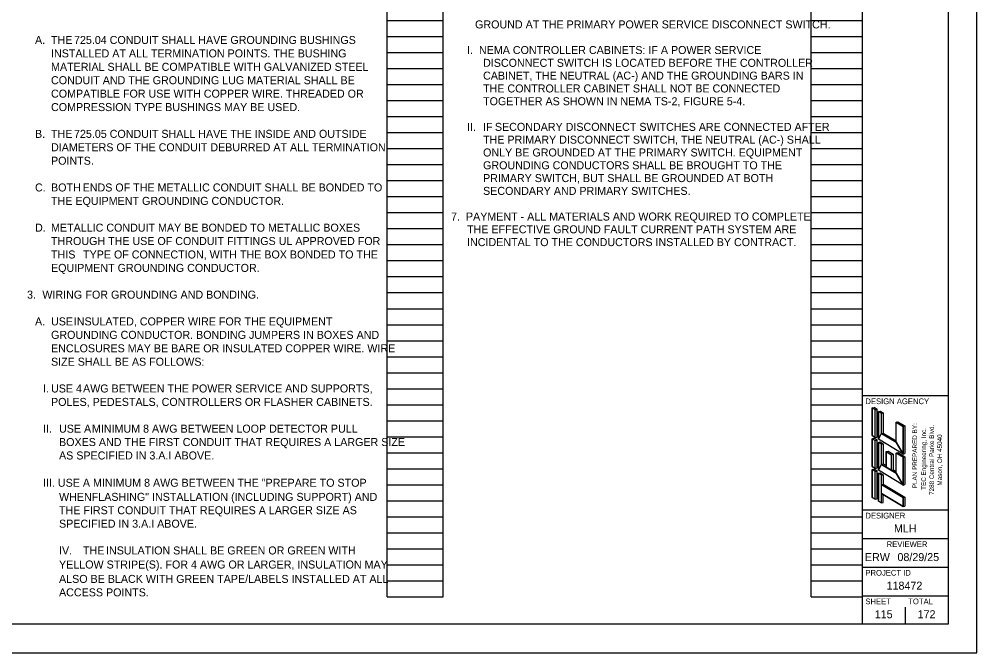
# Model space of a CAD drawing. Extents: x 0 to 34, y 0 to 22.
# Drawn here: x 17.24 to 34, y 0 to 11.08 of the extents above; entities that cross this region are included whole.
import ezdxf

# ---------------------------------------------------------------- set-up
doc = ezdxf.new("R2010")
doc.units = 0
for name, color, linetype in [('Default', 7, 'Continuous'), ('SH_Border', 7, 'Continuous'), ('SH_Cut_Line', 7, 'Continuous'), ('SH_Data', 7, 'Continuous'), ('SH_Text', 7, 'Continuous')]:
    doc.layers.add(name, color=color, linetype=linetype)

msp = doc.modelspace()

# ---------------------------------------------------------------- linework, layer by layer
at = {"layer": 'SH_Border'}
for p, q in [((32, 0.5), (32, 21.5)), ((32, 4.5), (33.5, 4.5)), ((32, 2.5), (33.5, 2.5)), ((32, 2), (33.5, 2)), ((32, 1.5), (33.5, 1.5)), ((32, 1), (33.5, 1))]:
    msp.add_line(p, q, dxfattribs=at)
msp.add_lwpolyline([(1.5, 21.5), (33.5, 21.5), (33.5, 0.5), (1.5, 0.5)], close=True, dxfattribs=at)
at = {"layer": 'SH_Cut_Line'}
msp.add_lwpolyline([(0, 0), (34, 0), (34, 22), (0, 22)], close=True, dxfattribs=at)
at = {"layer": 'SH_Data'}
for p, q in [((23.68, 0.98), (23.68, 21.14)), ((24.66, 0.98), (24.66, 21.14)), ((31.1, 0.98), (31.1, 21.14)), ((32, 0.98), (32, 21.14)), ((23.68, 11.06), (24.66, 11.06)), ((31.1, 11.06), (32, 11.06)), ((23.68, 10.78), (24.66, 10.78)), ((31.1, 10.78), (32, 10.78)), ((23.68, 10.5), (24.66, 10.5)), ((31.1, 10.5), (32, 10.5)), ((23.68, 10.22), (24.66, 10.22)), ((31.1, 10.22), (32, 10.22)), ((23.68, 9.94), (24.66, 9.94)), ((31.1, 9.94), (32, 9.94)), ((23.68, 9.66), (24.66, 9.66)), ((31.1, 9.66), (32, 9.66)), ((23.68, 9.38), (24.66, 9.38)), ((31.1, 9.38), (32, 9.38)), ((23.68, 9.1), (24.66, 9.1)), ((31.1, 9.1), (32, 9.1)), ((23.68, 8.82), (24.66, 8.82)), ((31.1, 8.82), (32, 8.82)), ((23.68, 8.54), (24.66, 8.54)), ((31.1, 8.54), (32, 8.54)), ((23.68, 8.26), (24.66, 8.26)), ((31.1, 8.26), (32, 8.26)), ((23.68, 7.98), (24.66, 7.98)), ((31.1, 7.98), (32, 7.98)), ((23.68, 7.7), (24.66, 7.7)), ((31.1, 7.7), (32, 7.7)), ((23.68, 7.42), (24.66, 7.42)), ((31.1, 7.42), (32, 7.42)), ((23.68, 7.14), (24.66, 7.14)), ((31.1, 7.14), (32, 7.14)), ((23.68, 6.86), (24.66, 6.86)), ((31.1, 6.86), (32, 6.86)), ((23.68, 6.58), (24.66, 6.58)), ((31.1, 6.58), (32, 6.58)), ((23.68, 6.3), (24.66, 6.3)), ((31.1, 6.3), (32, 6.3)), ((23.68, 6.02), (24.66, 6.02)), ((31.1, 6.02), (32, 6.02)), ((23.68, 5.74), (24.66, 5.74)), ((31.1, 5.74), (32, 5.74)), ((23.68, 5.46), (24.66, 5.46)), ((31.1, 5.46), (32, 5.46)), ((23.68, 5.18), (24.66, 5.18)), ((31.1, 5.18), (32, 5.18)), ((23.68, 4.9), (24.66, 4.9)), ((31.1, 4.9), (32, 4.9)), ((23.68, 4.62), (24.66, 4.62)), ((31.1, 4.62), (32, 4.62)), ((23.68, 4.34), (24.66, 4.34)), ((31.1, 4.34), (32, 4.34)), ((23.68, 4.06), (24.66, 4.06)), ((31.1, 4.06), (32, 4.06)), ((23.68, 3.78), (24.66, 3.78)), ((31.1, 3.78), (32, 3.78)), ((23.68, 3.5), (24.66, 3.5)), ((31.1, 3.5), (32, 3.5)), ((32.75, 3.5), (32.75, 3.5)), ((23.68, 3.22), (24.66, 3.22)), ((31.1, 3.22), (32, 3.22)), ((23.68, 2.94), (24.66, 2.94)), ((31.1, 2.94), (32, 2.94)), ((23.68, 2.66), (24.66, 2.66)), ((31.1, 2.66), (32, 2.66)), ((23.68, 2.38), (24.66, 2.38)), ((31.1, 2.38), (32, 2.38)), ((23.68, 2.1), (24.66, 2.1)), ((31.1, 2.1), (32, 2.1)), ((23.68, 1.82), (24.66, 1.82)), ((31.1, 1.82), (32, 1.82)), ((23.68, 1.54), (24.66, 1.54)), ((31.1, 1.54), (32, 1.54)), ((23.68, 1.26), (24.66, 1.26)), ((31.1, 1.26), (32, 1.26)), ((23.68, 0.98), (24.66, 0.98)), ((31.1, 0.98), (32, 0.98)), ((32.375, 0.675), (32.375, 0.675)), ((32.75, 0.5), (32.75, 0.8))]:
    msp.add_line(p, q, dxfattribs=at)
at = {"layer": 'SH_Text'}
for p, q in [((32.169, 4.285), (32.201, 4.294)), ((32.169, 3.799), (32.169, 4.285)), ((32.223, 4.253), (32.169, 4.285)), ((32.255, 4.261), (32.201, 4.294)), ((32.223, 4.253), (32.255, 4.261)), ((32.223, 3.767), (32.223, 4.253)), ((32.255, 3.775), (32.255, 4.261)), ((32.277, 4.221), (32.309, 4.229)), ((32.331, 4.188), (32.277, 4.221)), ((32.277, 3.735), (32.277, 4.221)), ((32.309, 4.229), (32.363, 4.196)), ((32.331, 4.188), (32.363, 4.196)), ((32.363, 4.196), (32.363, 3.845)), ((32.331, 3.837), (32.331, 4.188)), ((32.587, 4.034), (32.62, 4.042)), ((32.587, 3.683), (32.587, 4.034)), ((32.709, 3.961), (32.587, 4.034)), ((32.62, 4.042), (32.741, 3.97)), ((32.709, 3.961), (32.741, 3.97)), ((32.709, 3.475), (32.709, 3.961)), ((32.741, 3.97), (32.741, 3.484)), ((32.223, 3.767), (32.169, 3.799)), ((32.169, 3.745), (32.201, 3.754)), ((32.169, 3.259), (32.169, 3.745)), ((32.223, 3.713), (32.169, 3.745)), ((32.255, 3.722), (32.201, 3.754)), ((32.223, 3.767), (32.255, 3.775)), ((32.223, 3.713), (32.255, 3.722)), ((32.223, 3.227), (32.223, 3.713)), ((32.255, 3.236), (32.255, 3.722)), ((32.709, 3.475), (32.277, 3.735)), ((32.277, 3.681), (32.309, 3.689)), ((32.309, 3.689), (32.363, 3.656)), ((32.331, 3.837), (32.363, 3.845)), ((32.587, 3.683), (32.331, 3.837)), ((32.363, 3.845), (32.587, 3.711)), ((32.277, 3.195), (32.277, 3.681)), ((32.331, 3.648), (32.277, 3.681)), ((32.331, 3.648), (32.363, 3.656)), ((32.331, 3.297), (32.331, 3.648)), ((32.363, 3.656), (32.363, 3.305)), ((32.415, 3.519), (32.448, 3.527)), ((32.448, 3.527), (32.535, 3.474)), ((32.415, 3.519), (32.415, 3.247)), ((32.415, 3.519), (32.503, 3.466)), ((32.503, 3.466), (32.535, 3.474)), ((32.503, 3.466), (32.503, 3.194)), ((32.535, 3.474), (32.535, 3.202)), ((32.587, 3.494), (32.62, 3.502)), ((32.587, 3.143), (32.587, 3.494)), ((32.709, 3.421), (32.587, 3.494)), ((32.62, 3.502), (32.741, 3.43)), ((32.709, 3.475), (32.741, 3.484)), ((32.709, 3.421), (32.741, 3.43)), ((32.709, 2.935), (32.709, 3.421)), ((32.741, 3.43), (32.741, 2.944)), ((32.223, 3.227), (32.169, 3.259)), ((32.169, 3.205), (32.201, 3.215)), ((32.169, 2.719), (32.169, 3.205)), ((32.223, 3.173), (32.169, 3.205)), ((32.255, 3.181), (32.201, 3.215)), ((32.223, 3.227), (32.255, 3.236)), ((32.709, 2.935), (32.277, 3.195)), ((32.331, 3.297), (32.363, 3.305)), ((32.415, 3.247), (32.331, 3.297)), ((32.363, 3.305), (32.415, 3.274)), ((32.503, 3.194), (32.535, 3.202)), ((32.587, 3.143), (32.503, 3.194)), ((32.535, 3.202), (32.587, 3.171)), ((32.222, 3.173), (32.255, 3.181)), ((32.223, 2.687), (32.223, 3.173)), ((32.255, 2.695), (32.255, 3.181)), ((32.277, 3.141), (32.309, 3.151)), ((32.331, 3.108), (32.277, 3.141)), ((32.277, 2.655), (32.277, 3.141)), ((32.309, 3.151), (32.363, 3.116)), ((32.331, 3.108), (32.363, 3.116)), ((32.331, 2.944), (32.331, 3.108)), ((32.363, 3.116), (32.363, 2.952)), ((32.331, 2.944), (32.363, 2.952)), ((32.331, 2.944), (32.709, 2.717)), ((32.363, 2.952), (32.741, 2.725)), ((32.709, 2.935), (32.741, 2.944)), ((32.223, 2.687), (32.169, 2.719)), ((32.223, 2.687), (32.255, 2.695)), ((32.331, 2.787), (32.709, 2.56)), ((32.331, 2.622), (32.331, 2.787)), ((32.363, 2.63), (32.363, 2.767)), ((32.709, 2.717), (32.741, 2.725)), ((32.709, 2.56), (32.709, 2.717)), ((32.741, 2.725), (32.741, 2.568)), ((32.331, 2.622), (32.277, 2.655)), ((32.331, 2.622), (32.363, 2.63)), ((32.709, 2.56), (32.741, 2.568))]:
    msp.add_line(p, q, dxfattribs=at)
for points in [[(32.169, 3.799), (32.223, 3.767), (32.223, 4.253), (32.169, 4.285)], [(32.277, 3.735), (32.331, 3.837), (32.331, 4.188), (32.277, 4.221)], [(32.709, 3.475), (32.587, 3.683), (32.587, 4.034), (32.709, 3.961)], [(32.169, 3.259), (32.223, 3.227), (32.223, 3.713), (32.169, 3.745)], [(32.277, 3.735), (32.331, 3.837), (32.587, 3.683), (32.709, 3.475)], [(32.277, 3.195), (32.331, 3.297), (32.331, 3.648), (32.277, 3.681)], [(32.415, 3.247), (32.415, 3.519), (32.503, 3.466), (32.503, 3.194)], [(32.709, 2.935), (32.587, 3.143), (32.587, 3.494), (32.709, 3.421)], [(32.169, 2.719), (32.223, 2.687), (32.223, 3.173), (32.169, 3.205)], [(32.277, 3.195), (32.331, 3.297), (32.587, 3.143), (32.709, 2.935)], [(32.277, 2.655), (32.331, 2.622), (32.331, 3.108), (32.277, 3.141)], [(32.331, 2.787), (32.331, 2.944), (32.709, 2.717), (32.709, 2.56)]]:
    msp.add_lwpolyline(points, close=True, dxfattribs=at)

# ---------------------------------------------------------------- texts
at = {"layer": 'Default'}
for s, p in [('PLAN PREPARED BY:', (32.954, 2.88)), ('TEC Engineering, Inc.', (33.11, 2.851)), ('7288 Central Parke Blvd.', (33.25, 2.762)), ('Mason, OH 45040', (33.39, 2.925))]:
    msp.add_text(s, height=0.08, rotation=90, dxfattribs=at).set_placement(p)
at = {"layer": 'SH_Data'}
for s, height, p in [('DESIGN AGENCY', 0.1, (32.05, 4.35)), ('DESIGNER', 0.1, (32.05, 2.35)), ('MLH', 0.14, (32.55, 2.105)), ('REVIEWER', 0.1, (32.422, 1.85)), ('ERW', 0.14, (32.042, 1.605)), ('08/29/25', 0.14, (32.611, 1.605)), ('PROJECT ID', 0.1, (32.05, 1.35)), ('118472', 0.14, (32.421, 1.105)), ('SHEET', 0.1, (32.05, 0.85)), ('TOTAL', 0.1, (32.8, 0.85)), ('115', 0.14, (32.214, 0.605)), ('172', 0.14, (32.964, 0.605))]:
    msp.add_text(s, height=height, dxfattribs=at).set_placement(p)
at = {"layer": 'SH_Text'}
for s, p in [('GROUND AT THE PRIMARY POWER SERVICE DISCONNECT SWITCH.', (25.22, 10.922)), ('A.', (17.52, 10.65)), ('THE ', (17.8, 10.65)), ('725.04 CONDUIT SHALL HAVE GROUNDING BUSHINGS ', (18.202, 10.65)), ('I.  NEMA CONTROLLER CABINETS: IF A POWER SERVICE ', (25.08, 10.474)), ('INSTALLED AT ALL TERMINATION POINTS. THE BUSHING ', (17.8, 10.415)), ('DISCONNECT SWITCH IS LOCATED BEFORE THE CONTROLLER ', (25.36, 10.25)), ('MATERIAL SHALL BE COMPATIBLE WITH GALVANIZED STEEL ', (17.8, 10.18)), ('CONDUIT AND THE GROUNDING LUG MATERIAL SHALL BE ', (17.8, 9.946)), ('CABINET, THE NEUTRAL (AC-) AND THE GROUNDING BARS IN ', (25.36, 10.026)), ('THE CONTROLLER CABINET SHALL NOT BE CONNECTED ', (25.36, 9.802)), ('COMPATIBLE FOR USE WITH COPPER WIRE. THREADED OR ', (17.8, 9.711)), ('TOGETHER AS SHOWN IN NEMA TS-2, FIGURE 5-4.', (25.36, 9.578)), ('COMPRESSION TYPE BUSHINGS MAY BE USED.', (17.8, 9.476)), ('II.', (25.08, 9.13)), ('IF ', (25.36, 9.13)), ('SECONDARY DISCONNECT SWITCHES ARE CONNECTED AFTER ', (25.567, 9.13)), ('B.', (17.52, 9.008)), ('THE ', (17.8, 9.008)), ('725.05 CONDUIT SHALL HAVE THE INSIDE AND OUTSIDE ', (18.202, 9.008)), ('THE PRIMARY DISCONNECT SWITCH, THE NEUTRAL (AC-) SHALL ', (25.36, 8.906)), ('DIAMETERS OF THE CONDUIT DEBURRED AT ALL TERMINATION ', (17.8, 8.773)), ('ONLY BE GROUNDED AT THE PRIMARY SWITCH. EQUIPMENT ', (25.36, 8.682)), ('POINTS.', (17.8, 8.538)), ('GROUNDING CONDUCTORS SHALL BE BROUGHT TO THE ', (25.36, 8.458)), ('C.', (17.52, 8.07)), ('BOTH ', (17.8, 8.07)), ('ENDS OF THE METALLIC CONDUIT SHALL BE BONDED TO ', (18.353, 8.07)), ('PRIMARY SWITCH, BUT SHALL BE GROUNDED AT BOTH ', (25.36, 8.234)), ('SECONDARY AND PRIMARY SWITCHES.', (25.36, 8.01)), ('THE EQUIPMENT GROUNDING CONDUCTOR.', (17.8, 7.835)), ('7.  PAYMENT - ALL MATERIALS AND WORK REQUIRED TO COMPLETE ', (24.8, 7.562)), ('D.', (17.52, 7.367)), ('METALLIC CONDUIT MAY BE BONDED TO METALLIC BOXES ', (17.8, 7.367)), ('THE EFFECTIVE GROUND FAULT CURRENT PATH SYSTEM ARE ', (25.08, 7.338)), ('THROUGH THE USE OF CONDUIT FITTINGS UL APPROVED FOR ', (17.8, 7.133)), ('INCIDENTAL TO THE CONDUCTORS INSTALLED BY CONTRACT.', (25.08, 7.114)), ('THIS ', (17.8, 6.898)), ('TYPE OF CONNECTION, WITH THE BOX BONDED TO THE ', (18.36, 6.898)), ('EQUIPMENT GROUNDING CONDUCTOR.', (17.8, 6.663)), ('3.', (17.38, 6.195)), ('  WIRING ', (17.544, 6.195)), ('FOR GROUNDING AND BONDING.', (18.402, 6.195)), ('A.', (17.52, 5.727)), ('USE ', (17.8, 5.727)), ('INSULATED, COPPER WIRE FOR THE EQUIPMENT ', (18.199, 5.727)), ('GROUNDING CONDUCTOR. BONDING JUMPERS IN BOXES AND ', (17.8, 5.492)), ('ENCLOSURES MAY BE BARE OR INSULATED COPPER WIRE. WIRE ', (17.8, 5.257)), ('SIZE SHALL BE AS FOLLOWS:', (17.8, 5.022)), ('I.', (17.66, 4.554)), ('USE 4 ', (17.8, 4.554)), ('AWG BETWEEN THE POWER SERVICE AND SUPPORTS, ', (18.36, 4.554)), ('POLES, PEDESTALS, CONTROLLERS OR FLASHER CABINETS.', (17.8, 4.319)), ('II.', (17.66, 3.851)), ('USE A ', (17.94, 3.851)), ('MINIMUM 8 AWG BETWEEN LOOP DETECTOR PULL ', (18.516, 3.851)), ('BOXES AND THE FIRST CONDUIT THAT REQUIRES A LARGER SIZE ', (17.94, 3.617)), ('AS SPECIFIED IN 3.A.I ABOVE.', (17.94, 3.382)), ('III. USE A MINIMUM 8 AWG BETWEEN THE "PREPARE TO STOP ', (17.66, 2.905)), ('WHENFLASHING" INSTALLATION (INCLUDING SUPPORT) AND ', (17.94, 2.658)), ('THE FIRST CONDUIT THAT REQUIRES A LARGER SIZE AS ', (17.94, 2.424)), ('SPECIFIED IN 3.A.I ABOVE.', (17.94, 2.189)), ('IV.', (17.94, 1.721)), ('THE ', (18.36, 1.721)), ('INSULATION SHALL BE GREEN OR GREEN WITH ', (18.762, 1.721)), ('YELLOW STRIPE(S). FOR 4 AWG OR LARGER, INSULATION MAY ', (17.94, 1.475)), ('ALSO BE BLACK WITH GREEN TAPE/LABELS INSTALLED AT ALL ', (17.94, 1.223)), ('ACCESS POINTS.', (17.94, 0.988))]:
    msp.add_text(s, height=0.14, dxfattribs=at).set_placement(p)

doc.saveas('drawing.dxf')
